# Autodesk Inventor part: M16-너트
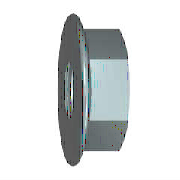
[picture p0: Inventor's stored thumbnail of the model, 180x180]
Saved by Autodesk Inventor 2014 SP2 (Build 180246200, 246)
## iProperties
IsCustomPart: 0
Company: 한국ATC센터
Created: 2009-02
Part Number: M16-너트
Material: Steel, Mild
Description: 플랜지붙이 6각 너트
Document SubType Name: Modeling
Standard: JIS B 1190
Designer: KYOUNG IL JANG
Standards Organization: JIS
Language: ko-KR
Size Designation: M 16
Categories: <MemberInstance><Categories><Category DisplayName="조임쇠" InternalName="e4da775c-781d-43d5-af7c-5136215cf5a6" Mnemonic="FSTN"><Category DisplayName="너트" InternalN
Density: 1 g/cm^3
Appearance: Metal-Steel
Author: KYOUNG IL JANG
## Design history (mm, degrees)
sketch "스케치1"
  geometry: L1 (-3.414, 0)-(18.069, 0) reference; L2 (6.015, 11)-(3.359, 15.6); L3 (6.015, 11)-(15, 11); L4 (15, 11)-(15, 0); L5 (6.015, 11)-(6.015, 0); L6 (0, -3.378)-(0, 20.266) reference; A1 r 1.8 centre (1.8, 14.7) between (3.359, 15.6) and (0, 14.7); 1 further point
  constraints: 8 end point, 3 point on line, 2 perpendicular, 2 point on circle, 2 tangent, 1 centre point, 1 parallel
  dimensions: "d2" = 22 diameter of L3 L1 (= SW); "d4" = 33 dimension on A1 L1 (= LADI); "d5" = 1.8 radius of A1 (= PHH); "d15" = 15 distance between parallel lines of L4 L6 (= KOH); "d16" = 30 deg angle of L6 L2 (= KEWI)
revolve "링" sketch "스케치1" stored, may be unused: angle "d8" = 90 deg
sketch "스케치2"
  geometry: L1 (-11, -6.351)-(-11, 6.351); L2 (-11, 6.351)-(0, 12.702); L3 (0, 12.702)-(11, 6.351); L4 (11, 6.351)-(11, -6.351); L5 (11, -6.351)-(0, -12.702); L6 (0, -12.702)-(-11, -6.351); C1 r 4.9 at (0, 0); C2 r 14.7 at (0, 0) reference; 1 further point
  constraints: 12 end point, 1 centre point, 1 coincident, 1 vertical, 11 other
  dimensions: "d6" = 25.40341 distance of L5.end L2.end (= 1.1547 x SW)
extrude "본체" join sketch "스케치2" distance "d7" = 15 (= KOH); taper "d9" = 0 deg
sketch "스케치3"
  geometry: L1 (5.032, 12.702)-(15, 12.702) reference; L2 (15, 6.351)-(15, 12.702) reference; L3 (0, -14.7)-(0, 14.7) reference; L4 (-3, 0)-(18, 0) reference; L5 (14.018, 12.702)-(15, 11)
  constraints: 2 end point, 2 point on line
  dimensions: "d10" = 30 deg angle of L2 L5 (= ANG1); "d11" = 22 diameter of L5.end L4 (= SW0)
revolve "모따기1" sketch "스케치3" stored, may be unused: angle "d24" = 90 deg
sketch "스케치4"
  geometry: C1 r 14.7 at (0, 0) reference; 1 further point
  constraints: 1 coincident
hole "스레드" sketch "스케치4" at (0, 0) diameter "d25" = 13.835; stored, may be unused: countersink angle "d29" = 82 deg, drill point angle "d31" = 118 deg; dims "d26" = 6, "d27" = 4, "d28" = 2, "d30" = 8
workaxis "Work Axis1"
workplane "Work Plane1"
body "Solid1"
chamfer "모따기2" distance "d12" = 1.08253 (= -0.5 x GD1 + 0.5 x NND); stored, may be unused: angle "d13" = 30 deg, second distance "d46" = 1.08253 (= -0.5 x GD1 + 0.5 x NND)
chamfer "모따기3" distance "d51" = 1.08253 (= -0.5 x GD1 + 0.5 x NND); stored, may be unused: second distance "d52" = 2, angle "d53" = 45 deg
other parameters: "ANG1" = 30 deg [user parameter; used in 1 equation term], "KEWI" = 30 deg [user parameter; used in 1 equation term], "NND" = 16 [user parameter; used in 3 equation terms], "LADI" = 33 [user parameter; used in 2 equation terms], "SW" = 22 [user parameter; used in 4 equation terms], "PHH" = 1.8 [user parameter; used in 2 equation terms], "KOH" = 15 [user parameter; used in 2 equation terms], "SW0" = 22 (= SW) [user parameter; used in 1 equation term], "GD1" = 13.83494 (computed from THREADDIA, PTC, TOA) [user parameter; used in 3 equation terms], "d1" = 33 (= LADI), "d3" = 1.8 (= PHH), "d45" = 0, "d47" = 0, "d49" = 0, "d54" = 0, "GUL" = 1.08253 (= 0.541266 x PTC) [user parameter], "TPU" = 5 (computed from PTC) [user parameter], "RR" = 2 [user parameter], "THREADDIA" = 16 [user parameter; used in 1 equation term], "TOA" = 30 deg [user parameter; used in 1 equation term], "PTC" = 2 [user parameter; used in 4 equation terms], "GAL" = 1.08253 (= 0.541266 x PTC) [user parameter], "E0" = 25.41 (= 1.155 x SW) [user parameter]
